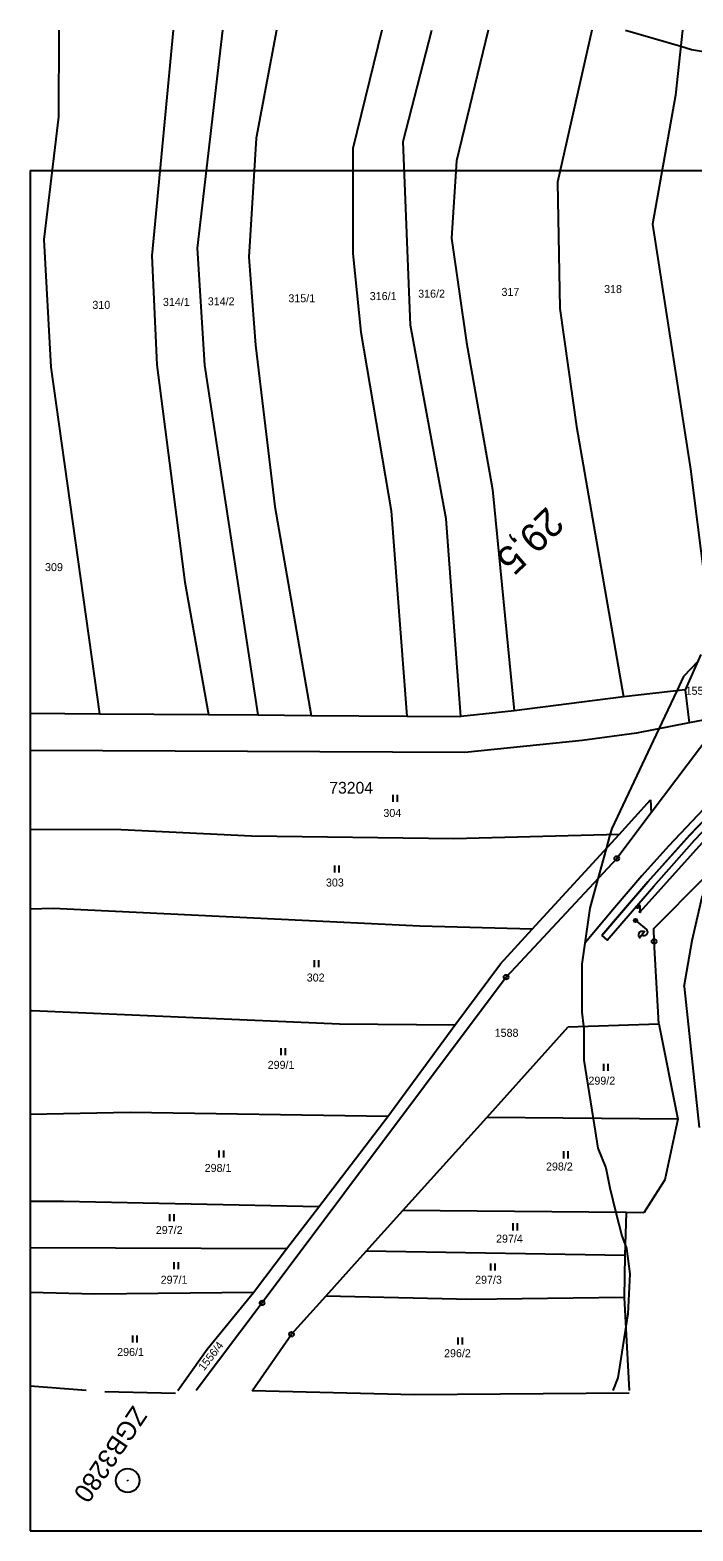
# Model space of a CAD drawing. Extents: x -756640 to -756220, y -1116060 to -1115741.
# Drawn here: x -756640.1 to -756499.3, y -1116060 to -1115741.2 of the extents above; entities that cross this region are included whole.
import ezdxf

# ---------------------------------------------------------------- set-up
doc = ezdxf.new("R2010")
doc.units = 0
for name, color, linetype in [('BPEJ', 7, 'Continuous'), ('GD_Demolice', 7, 'Continuous'), ('GD_Nový stav', 7, 'Continuous'), ('GD_Starý stav', 7, 'Continuous'), ('Katastr_HRANICE DRÁHY', 7, 'Continuous'), ('Katastr_Hranice parcel', 7, 'Continuous'), ('Katastr_Parcelní čísla', 7, 'Continuous'), ('Katastr_Značky kultur', 7, 'Continuous'), ('Vrstva 7', 7, 'Continuous'), ('ŽBP', 7, 'Continuous')]:
    doc.layers.add(name, color=color, linetype=linetype)

msp = doc.modelspace()

# ---------------------------------------------------------------- linework, layer by layer
at = {"layer": 'BPEJ'}
for points in [[(-756513.58, -1115741.18), (-756501.87, -1115744.61), (-756499.55, -1115745.29), (-756480.27, -1115748.57)], [(-756498.24, -1115875.3), (-756501.24, -1115878.53), (-756502.68, -1115881.57), (-756506.49, -1115889.6), (-756516.52, -1115910.78), (-756516.89, -1115912.13), (-756517.71, -1115915.1), (-756519.46, -1115921.46), (-756521.19, -1115927.75), (-756522.88, -1115939.63), (-756522.88, -1115949.82), (-756522.51, -1115952.82), (-756522.46, -1115953.21), (-756522.46, -1115960), (-756520.49, -1115972.39), (-756519.49, -1115978.67), (-756517.79, -1115982.91), (-756516.94, -1115987.16), (-756515.64, -1115992.37), (-756514.4, -1115997.34), (-756513.69, -1115999.21), (-756513.4, -1116000), (-756512.7, -1116005.4), (-756513.13, -1116013.89), (-756513.54, -1116016.57), (-756515.25, -1116027.47), (-756516.3, -1116030.18)]]:
    msp.add_lwpolyline(points, dxfattribs=at)
at = {"layer": 'Defpoints'}
for p, q in [((-756640.13, -1115771.02), (-756640.13, -1116060.02)), ((-756640.13, -1115771.02), (-756220.13, -1115771.02)), ((-756640.13, -1116060.02), (-756220.13, -1116060.02))]:
    msp.add_line(p, q, dxfattribs=at)
at = {"layer": 'GD_Demolice'}
for p, q in [((-756511.62, -1115929.99), (-756511.55, -1115930.7)), ((-756511.34, -1115929.99), (-756511.27, -1115930.65)), ((-756511.19, -1115930.57), (-756509.16, -1115932.23)), ((-756509.49, -1115932.64), (-756510.72, -1115934.15))]:
    msp.add_line(p, q, dxfattribs=at)
msp.add_circle((-756511.48, -1115930.34), 0.375, dxfattribs=at)
msp.add_circle((-756511.48, -1115930.34), 0.375, dxfattribs=at)
for centre, start, end in [((-756510.11, -1115933.39), 50.1456, 231.5508), ((-756509.63, -1115932.81), 230.8482, 50.8482)]:
    msp.add_arc(centre, 0.75, start, end, dxfattribs=at)
at = {"layer": 'GD_Nový stav'}
for p, q in [((-756510.69, -1115927.37), (-756511.42, -1115927.37)), ((-756510.43, -1115928.62), (-756510.62, -1115928.43)), ((-756510.36, -1115928.54), (-756510.53, -1115928.37)), ((-756510.49, -1115928.36), (-756510.49, -1115927.37))]:
    msp.add_line(p, q, dxfattribs=at)
msp.add_lwpolyline([(-756510.49, -1115928.5), (-756494.73, -1115910.99), (-756491.19, -1115906.22), (-756486.18, -1115901.19), (-756481.67, -1115896.93), (-756478.14, -1115894.35), (-756473.87, -1115890.1), (-756473.74, -1115890.25)], dxfattribs=at)
msp.add_circle((-756510.49, -1115928.5), 0.141, dxfattribs=at)
msp.add_circle((-756510.49, -1115928.5), 0.141, dxfattribs=at)
for centre, start, end in [((-756511.06, -1115927.38), 179.2811, 0.6862), ((-756510.77, -1115927.37), 359.9837, 179.9837)]:
    msp.add_arc(centre, 0.281, start, end, dxfattribs=at)
at = {"layer": 'GD_Starý stav'}
for p, q in [((-756491.34, -1115900.62), (-756504.48, -1115914.54)), ((-756488.75, -1115900.48), (-756500.01, -1115912.23)), ((-756499.99, -1115912.26), (-756488.72, -1115900.49)), ((-756500.01, -1115912.23), (-756508.86, -1115922.14)), ((-756508.86, -1115922.11), (-756499.99, -1115912.26)), ((-756504.48, -1115914.54), (-756510.1, -1115920.87)), ((-756510.1, -1115920.87), (-756515.92, -1115927.62)), ((-756508.86, -1115922.14), (-756514.44, -1115928.61)), ((-756514.43, -1115928.61), (-756508.86, -1115922.11)), ((-756515.92, -1115927.62), (-756522.16, -1115935.06)), ((-756514.44, -1115928.61), (-756518.65, -1115933.56)), ((-756518.61, -1115933.55), (-756514.43, -1115928.61)), ((-756518.65, -1115933.56), (-756518.61, -1115933.55))]:
    msp.add_line(p, q, dxfattribs=at)
msp.add_lwpolyline([(-756518.61, -1115933.55), (-756517.48, -1115934.49), (-756513.05, -1115929.32), (-756507.59, -1115923.05), (-756498.92, -1115913.24), (-756487.78, -1115901.64), (-756474.28, -1115888.97), (-756473.57, -1115888.27), (-756474.6, -1115887.22)], dxfattribs=at)
at = {"layer": 'Katastr_HRANICE DRÁHY'}
for points in [[(-756492.66, -1115886.9), (-756508.12, -1115907.44)], [(-756508.12, -1115907.44), (-756515.44, -1115917.16)], [(-756507.58, -1115932.04), (-756486.16, -1115910.54)], [(-756515.44, -1115917.16), (-756538.98, -1115942.37)], [(-756507.51, -1115934.79), (-756507.58, -1115932.04)], [(-756506.52, -1115952.32), (-756507.51, -1115934.79)], [(-756538.98, -1115942.37), (-756590.81, -1116011.58)], [(-756543.09, -1115972.17), (-756525.76, -1115952.92)], [(-756525.76, -1115952.92), (-756506.52, -1115952.32)], [(-756560.88, -1115991.93), (-756543.09, -1115972.17)], [(-756568.7, -1116000.61), (-756560.88, -1115991.93)], [(-756577.29, -1116010.16), (-756568.7, -1116000.61)], [(-756590.81, -1116011.58), (-756604.86, -1116030.18)], [(-756584.56, -1116018.23), (-756577.29, -1116010.16)], [(-756592.94, -1116030.24), (-756584.56, -1116018.23)]]:
    msp.add_lwpolyline(points, dxfattribs=at)
at = {"layer": 'Katastr_Hranice parcel'}
for points in [[(-756633.99, -1115741.18), (-756634.11, -1115759.63)], [(-756609.72, -1115741.18), (-756614.22, -1115789.17)], [(-756599.26, -1115741.18), (-756604.61, -1115787.49)], [(-756587.74, -1115741.18), (-756592.1, -1115764.13)], [(-756565.34, -1115741.18), (-756571.55, -1115766.34)], [(-756560.85, -1115764.89), (-756554.76, -1115741.18)], [(-756542.77, -1115741.18), (-756549.48, -1115768.99)], [(-756520.77, -1115741.18), (-756528.05, -1115773.51)], [(-756501.5, -1115741.18), (-756503, -1115755.02)], [(-756503, -1115755.02), (-756507.83, -1115782.44)], [(-756634.11, -1115759.63), (-756637.22, -1115785.67)], [(-756592.1, -1115764.13), (-756593.62, -1115789.44)], [(-756571.55, -1115766.34), (-756571.55, -1115788.68)], [(-756559.27, -1115803.88), (-756560.85, -1115764.89)], [(-756549.48, -1115768.99), (-756550.54, -1115785.37)], [(-756528.05, -1115773.51), (-756527.58, -1115800.34)], [(-756507.83, -1115782.44), (-756499.77, -1115834.45)], [(-756637.22, -1115785.67), (-756635.7, -1115812.82)], [(-756550.54, -1115785.37), (-756547.37, -1115807.58)], [(-756614.22, -1115789.17), (-756613.17, -1115812.3)], [(-756604.61, -1115787.49), (-756603.02, -1115812.4)], [(-756593.62, -1115789.44), (-756592.23, -1115808.14)], [(-756571.55, -1115788.68), (-756569.87, -1115805.33)], [(-756527.58, -1115800.34), (-756524.02, -1115825.38)], [(-756569.87, -1115805.33), (-756563.4, -1115843.32)], [(-756551.73, -1115844.98), (-756559.27, -1115803.88)], [(-756592.23, -1115808.14), (-756588.14, -1115842.37)], [(-756547.37, -1115807.58), (-756541.83, -1115838.76)], [(-756635.7, -1115812.82), (-756625.35, -1115886.44)], [(-756613.17, -1115812.3), (-756607.26, -1115858.45)], [(-756603.02, -1115812.4), (-756591.7, -1115886.68)], [(-756524.02, -1115825.38), (-756514.03, -1115882.86)], [(-756499.77, -1115834.45), (-756496.86, -1115857.44)], [(-756541.83, -1115838.76), (-756537.22, -1115885.77)], [(-756588.14, -1115842.37), (-756580.37, -1115886.76)], [(-756563.4, -1115843.32), (-756560.05, -1115886.9)], [(-756548.56, -1115886.98), (-756551.73, -1115844.98)], [(-756607.26, -1115858.45), (-756602.17, -1115886.61)], [(-756497.58, -1115873.81), (-756500.95, -1115881.37)], [(-756500.95, -1115881.37), (-756514.03, -1115882.86)], [(-756500.95, -1115881.37), (-756500.09, -1115888.35)], [(-756514.03, -1115882.86), (-756537.22, -1115885.77)], [(-756640.13, -1115886.33), (-756625.35, -1115886.44)], [(-756625.35, -1115886.44), (-756602.17, -1115886.61)], [(-756602.17, -1115886.61), (-756591.7, -1115886.68)], [(-756591.7, -1115886.68), (-756580.37, -1115886.76)], [(-756580.37, -1115886.76), (-756560.05, -1115886.9)], [(-756560.05, -1115886.9), (-756548.56, -1115886.98)], [(-756537.22, -1115885.77), (-756548.56, -1115886.98)], [(-756500.09, -1115888.35), (-756511.29, -1115890.54)], [(-756492.66, -1115886.9), (-756500.09, -1115888.35)], [(-756511.29, -1115890.54), (-756522.79, -1115892.12)], [(-756547.76, -1115894.63), (-756640.13, -1115894.26)], [(-756522.79, -1115892.12), (-756547.76, -1115894.63)], [(-756514.93, -1115912.08), (-756508.25, -1115904.68)], [(-756508.25, -1115904.68), (-756508.12, -1115907.44)], [(-756620.78, -1115911.11), (-756640.13, -1115911.02)], [(-756593.04, -1115912.43), (-756620.78, -1115911.11)], [(-756550.1, -1115912.96), (-756593.04, -1115912.43)], [(-756514.93, -1115912.08), (-756550.1, -1115912.96)], [(-756533.42, -1115932.16), (-756514.93, -1115912.08)], [(-756499.4, -1115934.6), (-756497.22, -1115925.01)], [(-756635.2, -1115927.8), (-756640.13, -1115927.95)], [(-756557.3, -1115931.53), (-756635.2, -1115927.8)], [(-756533.42, -1115932.16), (-756557.3, -1115931.53)], [(-756540.16, -1115939.57), (-756533.42, -1115932.16)], [(-756501.12, -1115944.34), (-756499.4, -1115934.6)], [(-756549.87, -1115952.58), (-756540.16, -1115939.57)], [(-756501.12, -1115944.34), (-756497.92, -1115974.28)], [(-756639.7, -1115949.54), (-756640.13, -1115949.54)], [(-756574.37, -1115952.38), (-756639.7, -1115949.54)], [(-756549.87, -1115952.58), (-756574.37, -1115952.38)], [(-756564.07, -1115971.94), (-756549.87, -1115952.58)], [(-756506.52, -1115952.32), (-756502.45, -1115972.57)], [(-756618.84, -1115971.15), (-756640.13, -1115971.58)], [(-756564.07, -1115971.94), (-756618.84, -1115971.15)], [(-756578.73, -1115991.17), (-756564.07, -1115971.94)], [(-756502.45, -1115972.57), (-756543.09, -1115972.17)], [(-756502.45, -1115972.57), (-756505.24, -1115985.42)], [(-756505.24, -1115985.42), (-756509.73, -1115992.43)], [(-756633.04, -1115990.05), (-756640.13, -1115990.03)], [(-756578.73, -1115991.17), (-756633.04, -1115990.05)], [(-756585.61, -1116000.09), (-756578.73, -1115991.17)], [(-756513.47, -1115992.39), (-756560.88, -1115991.93)], [(-756513.47, -1115992.39), (-756513.77, -1116001.5)], [(-756509.73, -1115992.43), (-756513.47, -1115992.39)], [(-756585.61, -1116000.09), (-756640.13, -1115999.84)], [(-756592.61, -1116009.35), (-756585.61, -1116000.09)], [(-756513.77, -1116001.5), (-756568.7, -1116000.61)], [(-756513.77, -1116001.5), (-756513.86, -1116010.4)], [(-756626.37, -1116009.68), (-756640.13, -1116009.34)], [(-756592.61, -1116009.35), (-756626.37, -1116009.68)], [(-756602.52, -1116021.37), (-756592.61, -1116009.35)], [(-756546.4, -1116010.82), (-756577.29, -1116010.16)], [(-756513.86, -1116010.4), (-756546.4, -1116010.82)], [(-756513.86, -1116010.4), (-756512.85, -1116030.18)], [(-756608.74, -1116030.18), (-756602.52, -1116021.37)], [(-756628.21, -1116030.18), (-756640.13, -1116029.29)], [(-756609.19, -1116030.82), (-756624.26, -1116030.47)], [(-756558.43, -1116031.12), (-756592.94, -1116030.24)], [(-756512.82, -1116030.77), (-756558.43, -1116031.12)]]:
    msp.add_lwpolyline(points, dxfattribs=at)
at = {"layer": 'Katastr_Značky kultur'}
for p, q in [((-756563.07, -1115903.63), (-756563.07, -1115905.13)), ((-756562.07, -1115905.13), (-756562.07, -1115903.63)), ((-756515.49, -1115917.16), (-756515.39, -1115917.16)), ((-756575.41, -1115918.67), (-756575.41, -1115920.17)), ((-756574.41, -1115920.17), (-756574.41, -1115918.67)), ((-756507.56, -1115934.79), (-756507.46, -1115934.79)), ((-756579.77, -1115938.73), (-756579.77, -1115940.23)), ((-756578.77, -1115940.23), (-756578.77, -1115938.73)), ((-756539.03, -1115942.37), (-756538.93, -1115942.37)), ((-756586.85, -1115957.48), (-756586.85, -1115958.98)), ((-756585.85, -1115958.98), (-756585.85, -1115957.48)), ((-756518.29, -1115960.8), (-756518.29, -1115962.3)), ((-756517.29, -1115962.3), (-756517.29, -1115960.8)), ((-756599.98, -1115979.21), (-756599.98, -1115980.71)), ((-756598.98, -1115980.71), (-756598.98, -1115979.21)), ((-756526.79, -1115979.37), (-756526.79, -1115980.87)), ((-756525.79, -1115980.87), (-756525.79, -1115979.37)), ((-756610.48, -1115992.74), (-756610.48, -1115994.24)), ((-756609.48, -1115994.24), (-756609.48, -1115992.74)), ((-756537.55, -1115994.66), (-756537.55, -1115996.16)), ((-756536.55, -1115996.16), (-756536.55, -1115994.66)), ((-756609.57, -1116002.94), (-756609.57, -1116004.44)), ((-756608.57, -1116004.44), (-756608.57, -1116002.94)), ((-756542.28, -1116003.22), (-756542.28, -1116004.72)), ((-756541.28, -1116004.72), (-756541.28, -1116003.22)), ((-756590.86, -1116011.58), (-756590.76, -1116011.58)), ((-756618.38, -1116018.48), (-756618.38, -1116019.98)), ((-756617.38, -1116019.98), (-756617.38, -1116018.48)), ((-756584.61, -1116018.23), (-756584.51, -1116018.23)), ((-756549.22, -1116018.91), (-756549.22, -1116020.41)), ((-756548.22, -1116020.41), (-756548.22, -1116018.91))]:
    msp.add_line(p, q, dxfattribs=at)
for centre in [(-756515.44, -1115917.16), (-756507.51, -1115934.79), (-756538.98, -1115942.37), (-756590.81, -1116011.58), (-756584.56, -1116018.23)]:
    msp.add_circle(centre, 0.499, dxfattribs=at)
at = {"layer": 'ŽBP'}
msp.add_line((-756619.3, -1116049.45), (-756619.45, -1116049.15), dxfattribs=at)
msp.add_circle((-756619.38, -1116049.3), 2.52, dxfattribs=at)

# ---------------------------------------------------------------- texts
at = {"layer": 'BPEJ'}
msp.add_text('73204', height=2.5, dxfattribs=at).set_placement((-756576.54, -1115903.39))
at = {"layer": 'Katastr_Parcelní čísla'}
for s, p in [('317', (-756539.95, -1115797.66)), ('318', (-756518.14, -1115797.05)), ('310', (-756626.88, -1115800.41)), ('314/1', (-756611.89, -1115799.79)), ('314/2', (-756602.36, -1115799.66)), ('315/1', (-756585.23, -1115799.01)), ('316/1', (-756567.94, -1115798.55)), ('316/2', (-756557.65, -1115798.03)), ('309', (-756636.94, -1115856.12)), ('1556/7', (-756500.82, -1115882.39)), ('304', (-756565.04, -1115908.34)), ('303', (-756577.25, -1115923.12)), ('302', (-756581.33, -1115943.3)), ('1588', (-756541.39, -1115955.05)), ('299/1', (-756589.63, -1115961.85)), ('299/2', (-756521.47, -1115965.21)), ('298/1', (-756603.02, -1115983.75)), ('298/2', (-756530.49, -1115983.45)), ('297/2', (-756613.4, -1115996.94)), ('297/4', (-756541.1, -1115998.78)), ('297/1', (-756612.37, -1116007.5)), ('297/3', (-756545.55, -1116007.5)), ('296/1', (-756621.61, -1116022.85)), ('296/2', (-756552.15, -1116023.11))]:
    msp.add_text(s, height=1.7, dxfattribs=at).set_placement(p)
msp.add_text('1556/4', height=1.7, rotation=52.3551, dxfattribs=at).set_placement((-756603.16, -1116026.13))
at = {"layer": 'Vrstva 7'}
msp.add_text('29,5', height=6, rotation=224.0682, dxfattribs=at).set_placement((-756530.3, -1115842.2))
at = {"layer": 'ŽBP'}
msp.add_text('ZGB3280', height=4, rotation=235.9674, dxfattribs=at).set_placement((-756618.27, -1116033.18))

doc.saveas('drawing.dxf')
